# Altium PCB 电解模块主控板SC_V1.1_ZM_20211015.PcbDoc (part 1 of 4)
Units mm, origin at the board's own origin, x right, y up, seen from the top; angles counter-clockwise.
Board outline 150.25 x 100.26 mm, 2 copper layers (Top Layer, Bottom Layer); 222 components, 167 nets, 677 pads, 2045 vias.
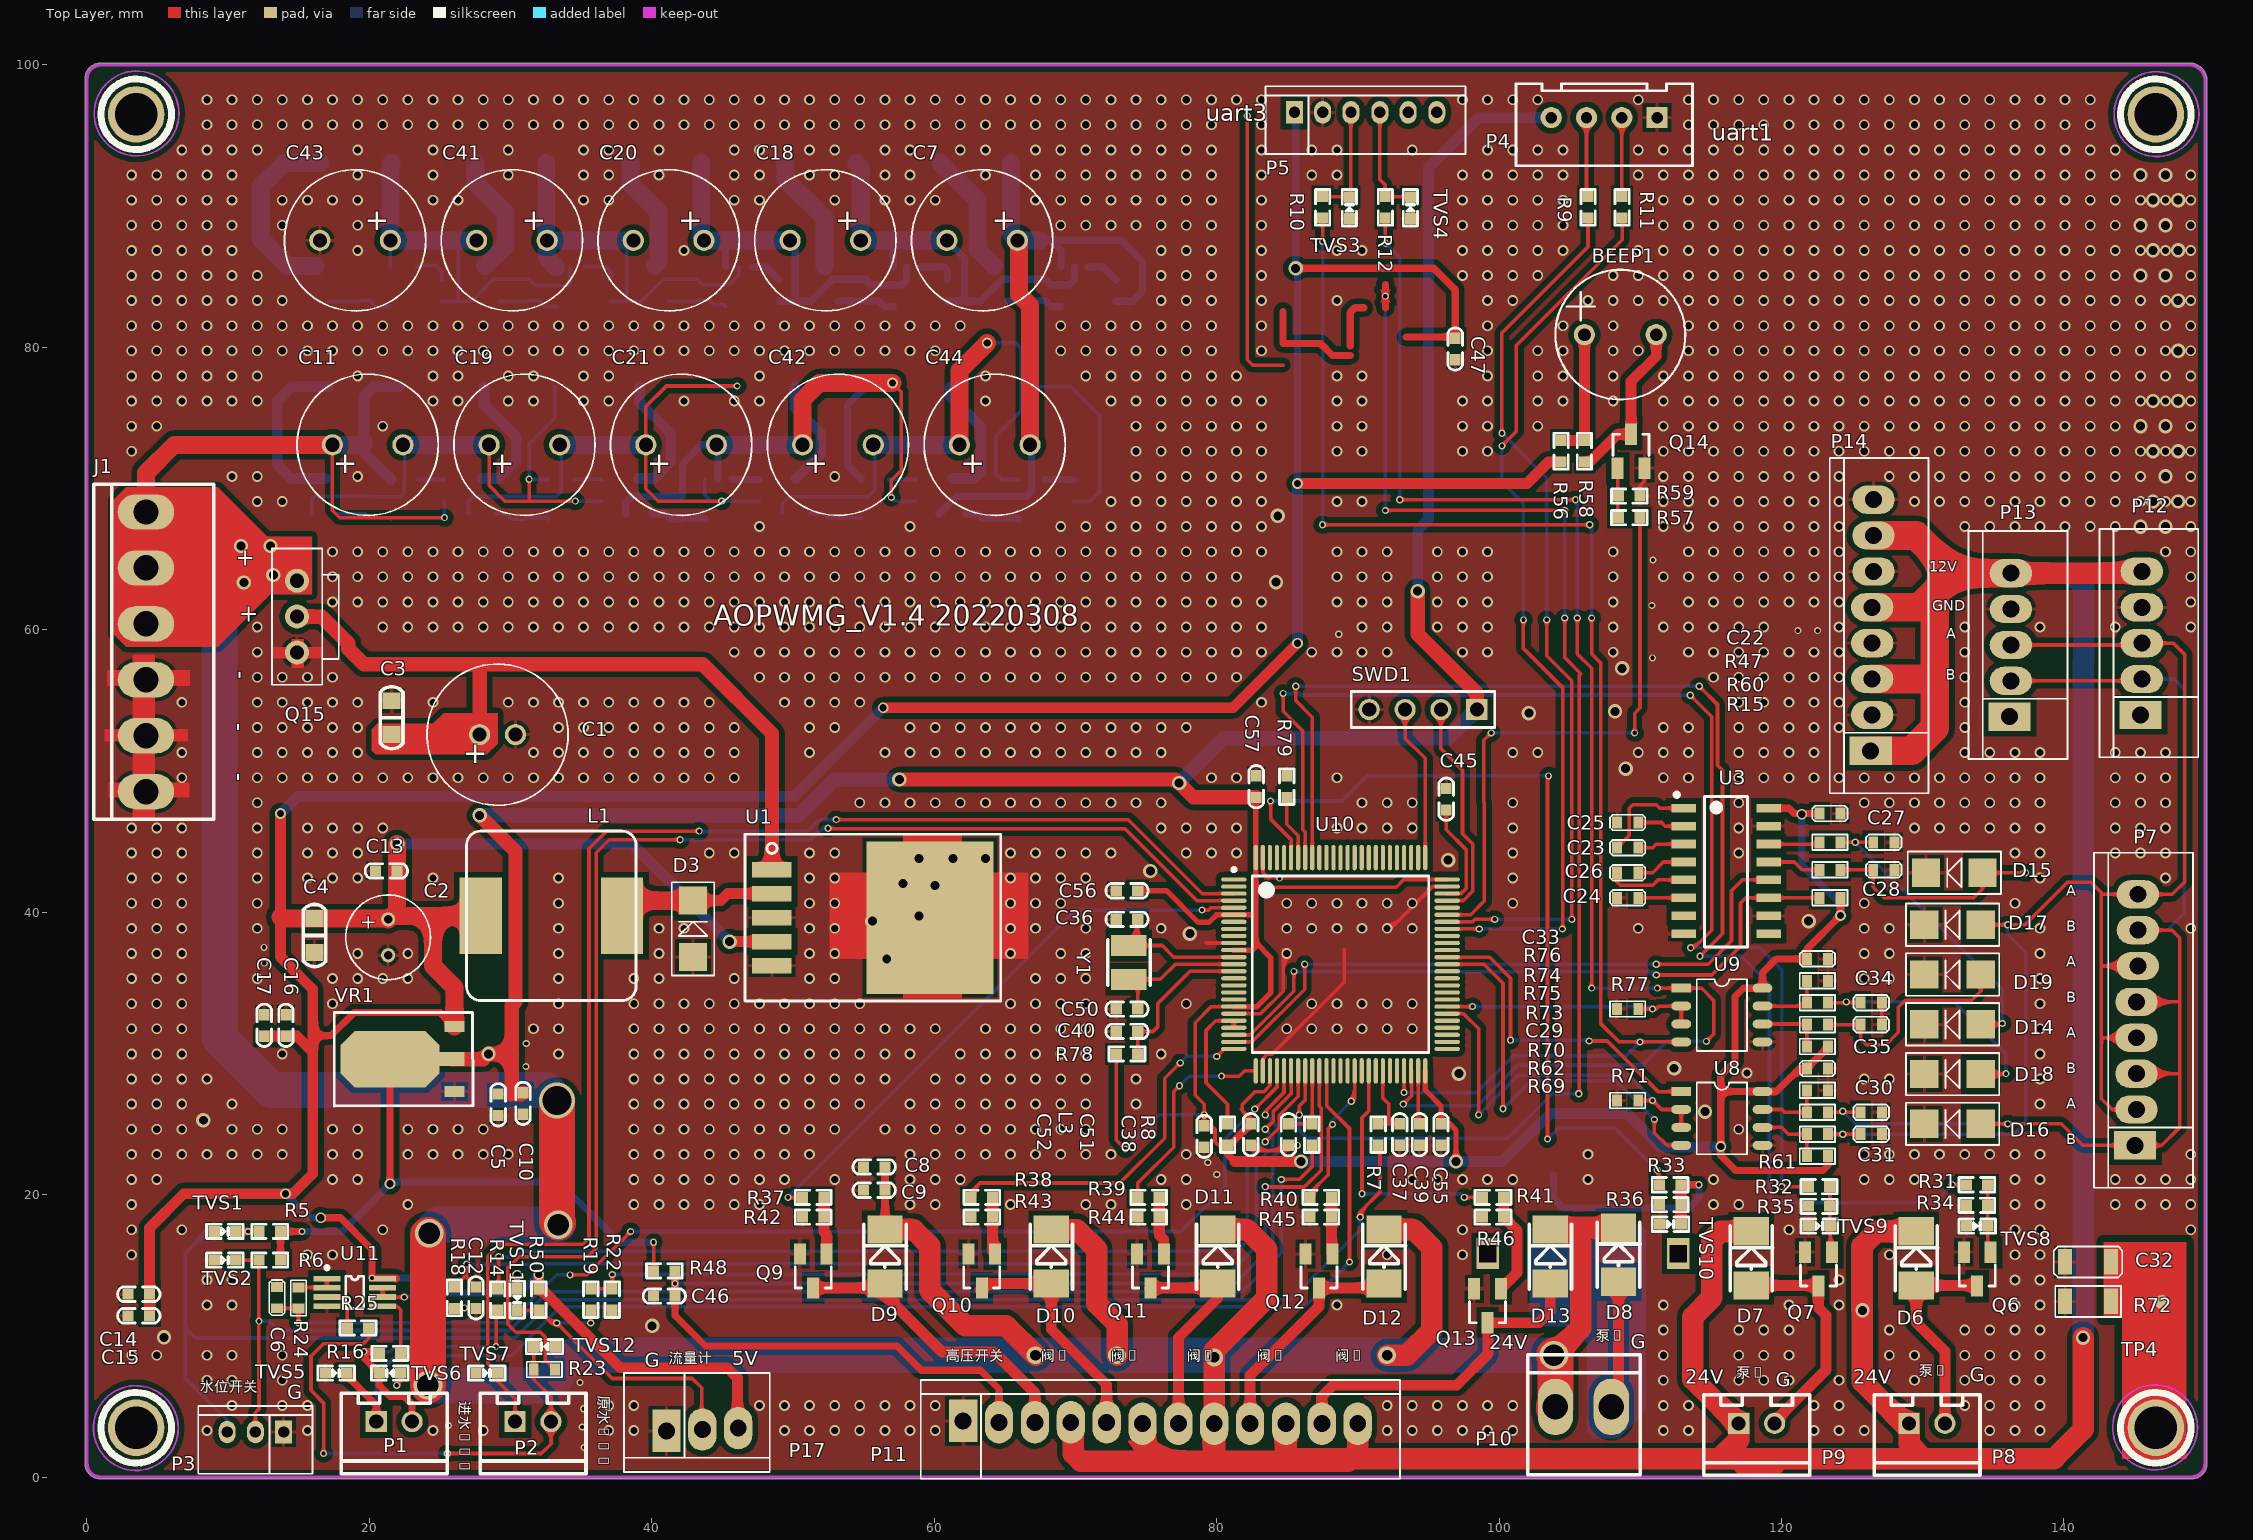
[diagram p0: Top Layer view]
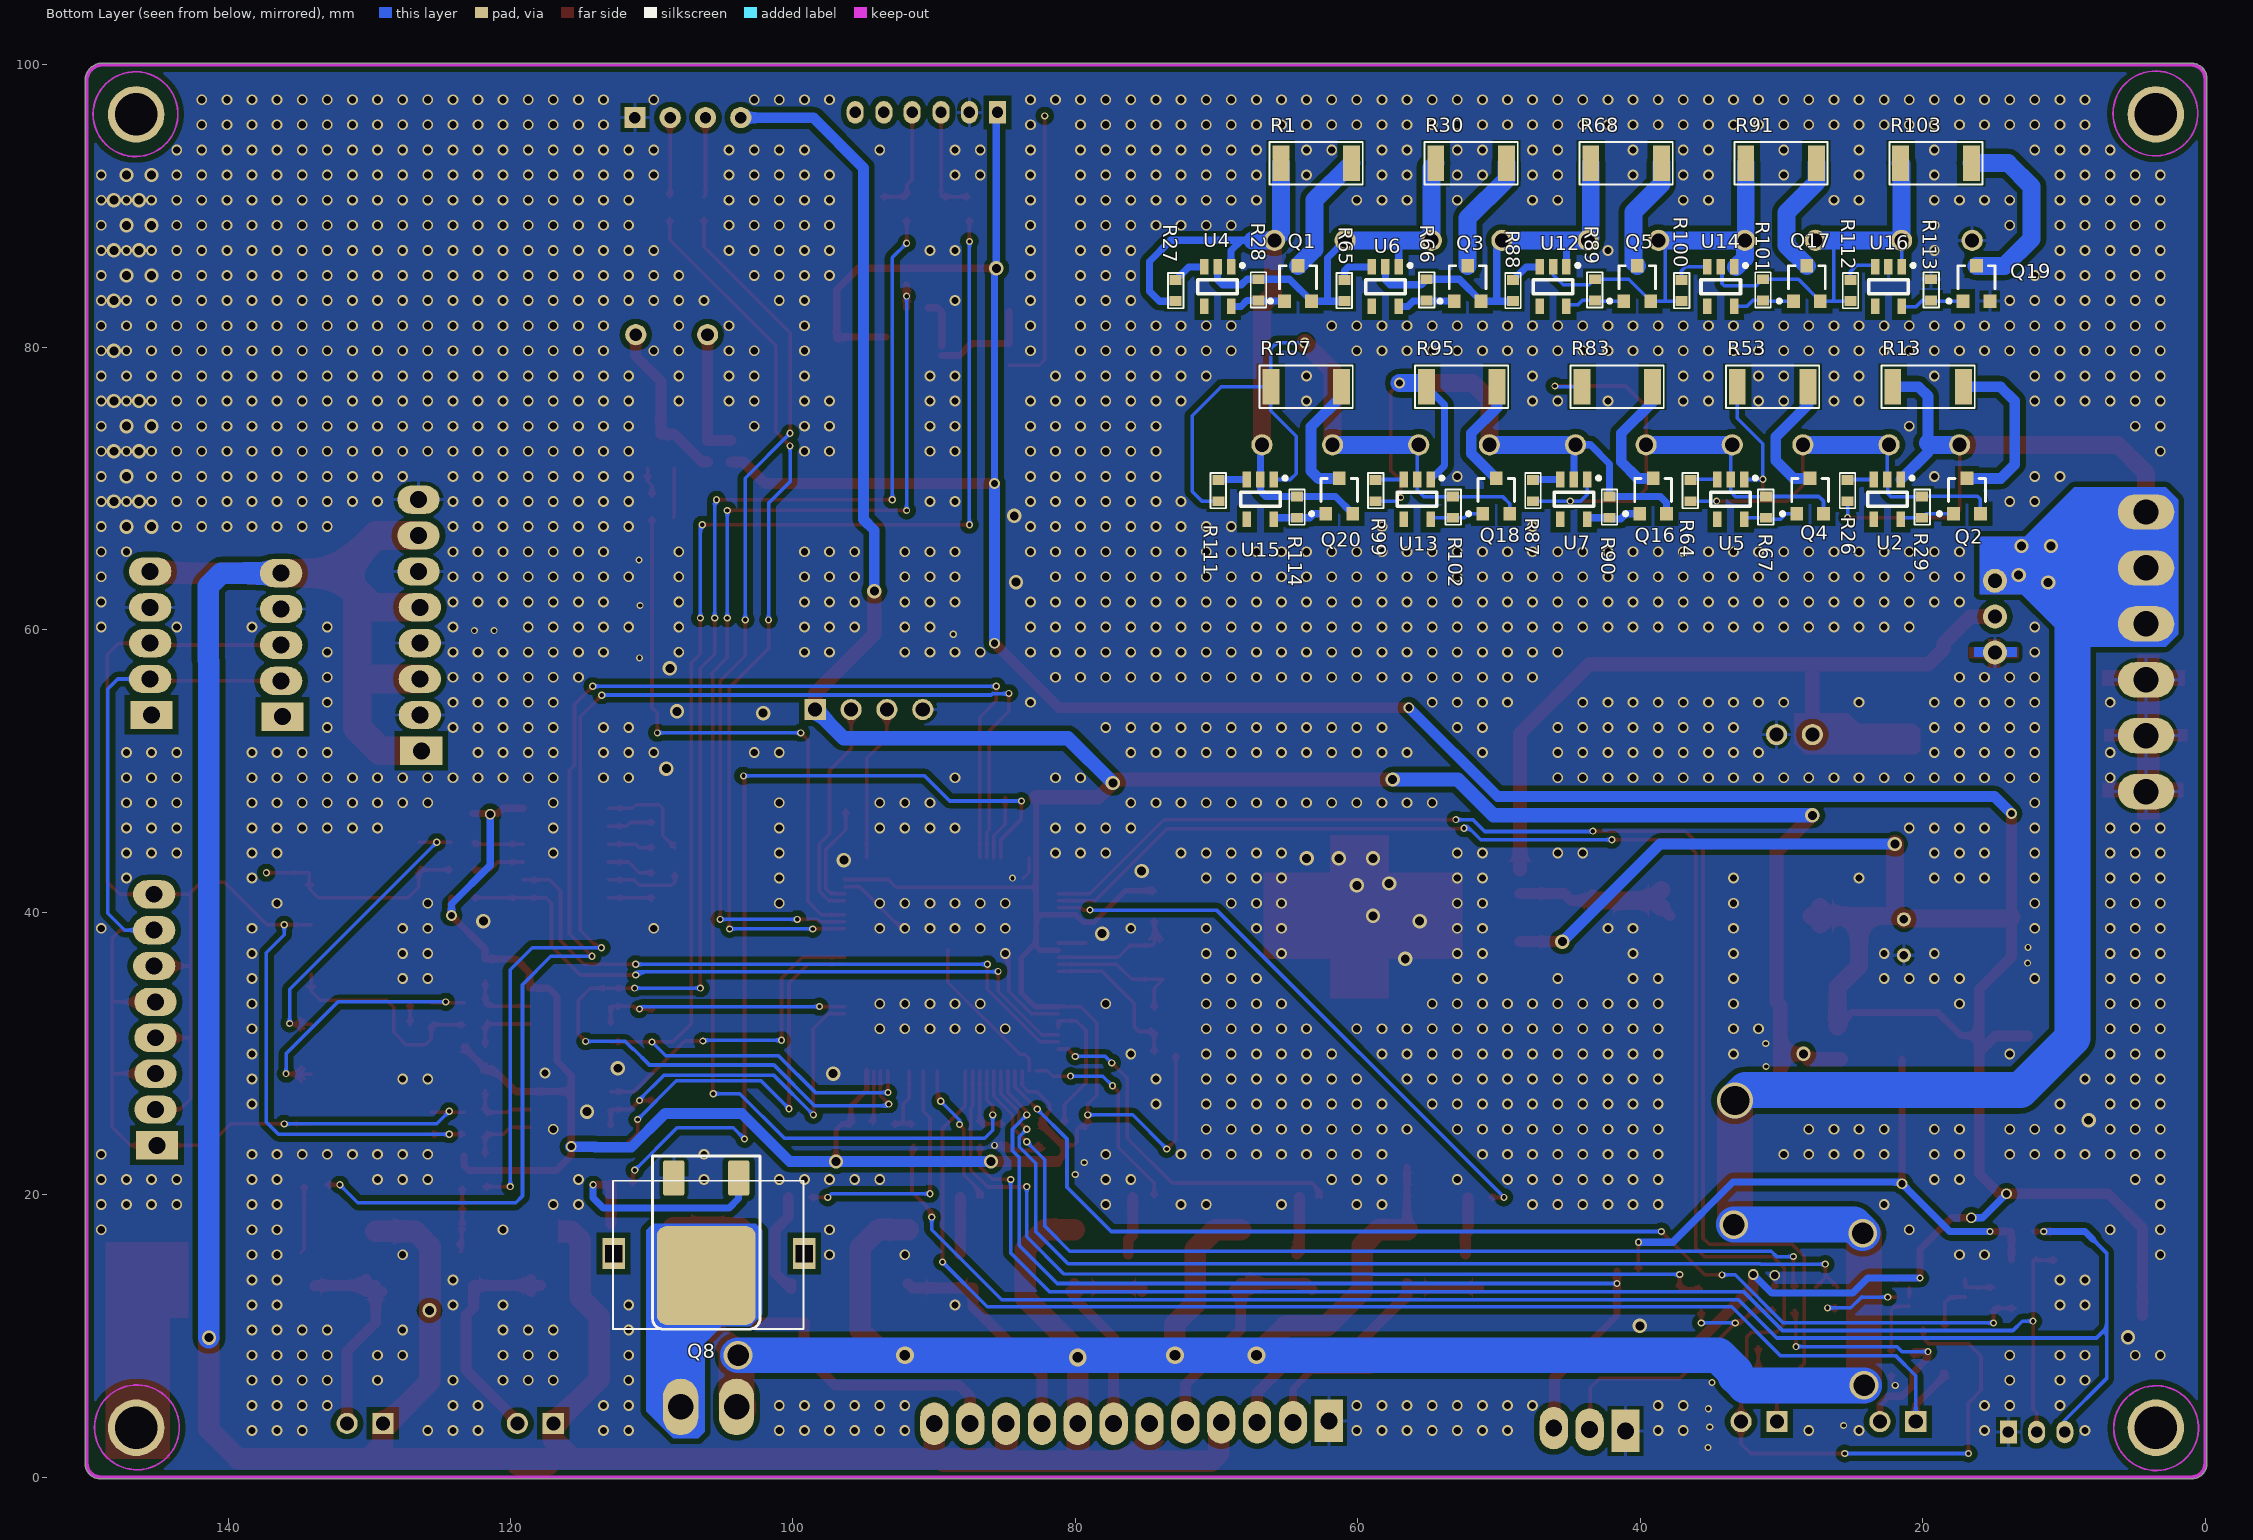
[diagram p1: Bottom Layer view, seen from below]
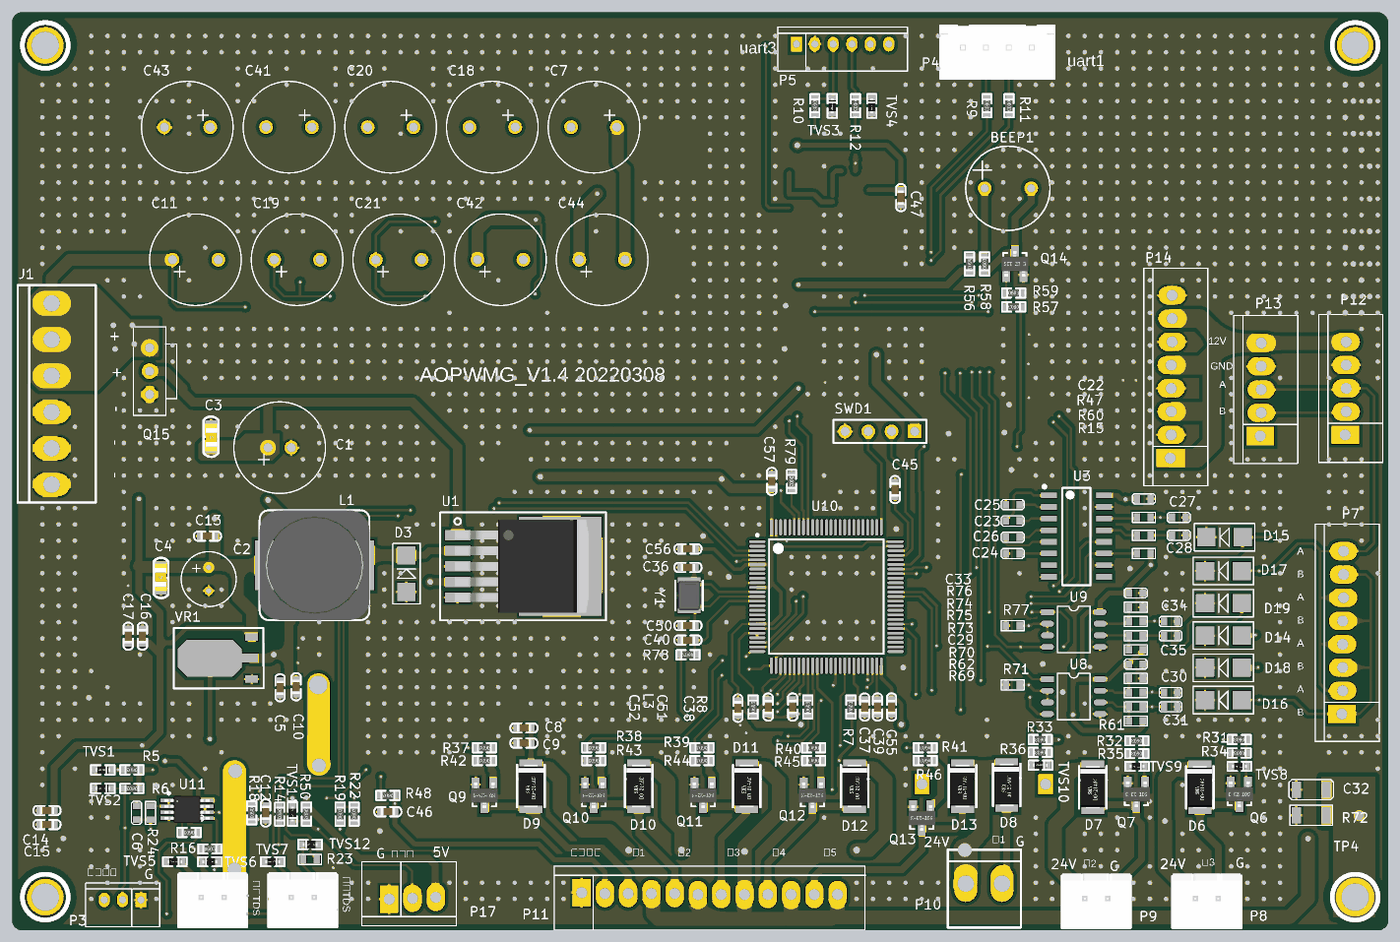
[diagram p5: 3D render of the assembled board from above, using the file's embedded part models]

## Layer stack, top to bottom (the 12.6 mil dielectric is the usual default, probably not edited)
Top Solder: solder mask 0.0102, Solder Resist, Dk 3.5
Top Layer: signal copper 0.0356
Dielectric1: dielectric 0.32, FR-4, Dk 4.8
Bottom Layer: signal copper 0.0356
Bottom Solder: solder mask 0.0102, Solder Resist, Dk 3.5

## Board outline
-0.127,1 ccw(c1,1) 1,-0.127 149,-0.127 ccw(c149,1) 150.127,1 150.127,99 ccw(c150,99) 150.126,99.016 ccw(c148.859,98.859) 148.709,100.127 1,100.127 ccw(c1,99) -0.127,99

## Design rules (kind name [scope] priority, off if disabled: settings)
Clearance Clearance_2 [InNet('NetC32_2')] p1: gap=0.508
Clearance Clearance_1 [InPolygon] p2: gap=0.381
Clearance [All] p3: gap=0.152
NetAntennae [All] p1: netantennaetolerance=5.08
PolygonConnect PolygonConnect_2 [InNet('NetC32_2')] p1: connectstyle=Direct reliefconductorwidth=0.254 reliefentries=4 polygonreliefangle="90 Angle" airgapwidth=0.254
PolygonConnect PolygonConnect_1 [isvia] p2: connectstyle=Direct reliefconductorwidth=0.254 reliefentries=4 polygonreliefangle="90 Angle" airgapwidth=0.254
PolygonConnect [All] p3: connectstyle=Relief reliefconductorwidth=0.254 reliefentries=4 polygonreliefangle="90 Angle" airgapwidth=0.254
RoutingVias [All] p1: holewidth=0.305 width=0.61 viastyle="Through Hole" minholewidth=0.203 minwidth=0.203 maxholewidth=5.08 maxwidth=5.08
SilkToSolderMaskClearance [IsPad] p1: minsilkscreentomaskgap=0.051 clearancetoexposedcopper=TRUE
SolderMaskExpansion [All] p1: expansion=0.102
Width [All] p1: maxlimit=9.144 minlimit=0.254 preferedwidth=0.254
28 further rules are at their usual default settings.

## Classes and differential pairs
component class 02_Power: C1 C2 C3 C4 C5 C8 C9 C10 C13 C14 C15 C16 C17 D3 J1 L1 Q15 U1 VR1
component class 04_Sensor: C6 C12 C37 C38 C47 P1 P2 P3 P17 R5 R6 R7 R8 R14 R16 R18 R19 R22 R23 R24 R25 R50 TVS1 TVS2 TVS5 TVS6 TVS7 TVS11 TVS12 U11
component class com: C22 C23 C24 C25 C26 C27 C28 C29 C30 C31 C32 C33 C34 C35 D14 D15 D16 D17 D18 D19 P7 P12 P13 P14 R15 R47 R60 R61 R62 R69 R70 R71 R72 R73 R74 R75 R76 R77 TP4 U3 U8 U9
component class 05_USART: P4 P5 R9 R10 R11 R12 TVS3 TVS4
component class cpu: C36 C39 C40 C45 C50 C51 C52 C55 C56 C57 L3 R78 R79 SWD1 U10 Y1
component class 08_Peripherals: C46 D6 D7 D8 D9 D10 D11 D12 D13 P8 P9 P10 P11 Q6 Q7 Q8 Q9 Q10 Q11 Q12 Q13 R31 R32 R33 R34 R35 R36 R37 R38 R39 R40 R41 R42 R43 R44 R45 R46 R48 TVS8 TVS9 TVS10
component class 11_Speak: BEEP1 BP1 Q14 R56 R57 R58 R59
component class 07_EL_CON: C7 C11 C18 C19 C20 C21 C41 C42 C43 C44 Q1 Q2 Q3 Q4 Q5 Q16 Q17 Q18 Q19 Q20 R1 R13 R26 R27 R28 R29 R30 R53 R64 R65 R66 R67 R68 R83 R87 R88 R89 R90 R91 R95 R99 R100 R101 R102 R103 R107 R111 R112 R113 R114 U2 U4 U5 U6 U7 U12 U13 U14 U15 U16

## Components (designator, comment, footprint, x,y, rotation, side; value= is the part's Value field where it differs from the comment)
BEEP1 "BEEP-9.5X5.5" BEEP-9.5X5.5 108.585,80.899 r0 top
C1 "1000uF/35V" 10*16 29.083,52.578 r180 top
C2 "100uF/35V" 6*8 21.336,38.227 r90 top
C3 "104 50V" SMD-0805C 21.59,53.778 r270 top
C4 "104 50V" SMD-0805C 16.129,38.354 r90 top
C5 "10uF 25V" SMD-0603C 29.134,26.365 r90 top
C6 "NC" 0603C 13.462,13.462 r270 top
C7 "1000uF/35V" "10*16 -5" 63.398,87.579 r0 top
C8 "10uF25V" SMD-0603C 55.753,21.971 r0 top
C9 "104 50V" SMD-0603C 55.753,20.32 r0 top
C10 "104 50V" SMD-0603C 30.886,26.467 r90 top
C11 "1000uF/35V" "10*16 -5" 19.888,73.101 r180 top
C12 "NC" SMD-0603C 27.559,12.7 r90 top
C13 "104 50V" SMD-0603C 21.209,42.926 r0 top
C14 "10uF25V" SMD-0603C 3.683,12.954 r0 top
C15 "104 50V" SMD-0603C 3.683,11.43 r0 top
C16 "10uF25V" SMD-0603C 14.097,31.991 r270 top
C17 "104 50V" SMD-0603C 12.56,31.991 r270 top
C18 "1000uF/35V" "10*16 -5" 52.299,87.579 r0 top
C19 "1000uF/35V" "10*16 -5" 30.988,73.101 r180 top
C20 "1000uF/35V" "10*16 -5" 41.199,87.579 r0 top
C21 "1000uF/35V" "10*16 -5" 42.088,73.101 r180 top
C22 "104 50V" 0603C 122.682,46.99 r0 top
C23 "104 50V" 0603C 108.355,44.577 r0 top
C24 "104 50V" 0603C 109.855,41.021 r180 top
C25 "104 50V" 0603C 109.855,46.355 r180 top
C26 "104 50V" 0603C 108.355,42.799 r0 top
C27 "220PF/16V" 0603C 126.492,44.958 r0 top
C28 "220PF/16V" 0603C 126.492,43.011 r0 top
C29 "104 50V" 0603C 121.793,28.942 r0 top
C30 "220PF/16V" 0603C 125.603,25.837 r0 top
C31 "220PF/16V" 0603C 125.603,24.285 r0 top
C32 "1NF/2KV" 1206C 140.081,15.24 r0 top
C33 "104 50V" 0603C 121.793,36.703 r0 top
C34 "220PF/16V" 0603C 125.603,33.599 r0 top
C35 "220PF/16V" 0603C 125.603,32.046 r0 top
C36 "12P/50V" SMD-0603C 73.66,39.497 r180 top
C37 "104 50V" SMD-0603C 92.964,24.257 r90 top
C38 "104 50V" SMD-0603C 85.09,24.257 r90 top
C39 "4.7uF/10V/NC" SMD-0603C 94.361,24.257 r90 top
C40 "1uF/10V" SMD-0603C 73.66,31.559 r0 top
C41 "1000uF/35V" "10*16 -5" 30.099,87.579 r0 top
C42 "1000uF/35V" "10*16 -5" 53.188,73.101 r180 top
C43 "1000uF/35V" "10*16 -5" 18.999,87.579 r0 top
C44 "1000uF/35V" "10*16 -5" 64.287,73.101 r180 top
C45 "4.7uF/10V/NC" SMD-0603C 96.266,48.006 r270 top
C46 "104 50V" SMD-0603C 40.894,12.827 r0 top
C47 "10uF 10V" SMD-0603C 96.901,79.883 r90 top
C50 "12P/50V" SMD-0603C 73.66,33.147 r180 top
C51 "104 50V" SMD-0603C 82.423,24.257 r90 top
C52 "104 50V" SMD-0603C 79.121,24.13 r90 top
C55 "104 50V" SMD-0603C 95.885,24.257 r90 top
C56 "104 50V" SMD-0603C 73.66,41.529 r0 top
C57 "104 50V" SMD-0603C 82.804,48.895 r270 top
D3 "SS34" SMA 42.926,36.83 r90 top
D6 "1N4007" DO-214-AC 129.54,15.494 r90 top
D7 "1N4007" DO-214-AC 117.856,15.494 r90 top
D8 "1N4007" DO-214-AC 108.458,15.748 r90 top
D9 "1N4007" DO-214-AC 56.515,15.621 r90 top
D10 "1N4007" DO-214-AC 68.294,15.621 r90 top
D11 "1N4007" DO-214-AC 80.073,15.621 r90 top
D12 "1N4007" DO-214-AC 91.853,15.621 r90 top
D13 "1N4007" DO-214-AC 103.632,15.621 r90 top
D14 "SMAJ18CA" SMA 134.112,32.067 r180 top
D15 "SMAJ18CA" SMA 134.239,42.799 r180 top
D16 "SMAJ6.5CA" SMA 134.112,25.019 r180 top
D17 "SMAJ6.5CA" SMA 134.112,39.116 r180 top
D18 "SMAJ6.5CA" SMA 134.112,28.543 r180 top
D19 "SMAJ6.5CA" SMA 134.112,35.592 r180 top
J1 "HEADER_6" VH-AW-3.96*6P 4.191,54.483 r90 top
L1 "CDRH127-33uH" CDRH-127 32.893,39.751 r180 top
L3 "MPZ1608D101BTA00" SMD-0603 80.772,24.257 r90 top
P1 "XH2.54 2P" SIP-2A 21.768,3.937 r0 top
P2 "XH2.54 2P" SIP-2A 31.598,3.937 r0 top
P3 "1*3P" 3X2MMZ 13.938,3.2 r180 top
P4 "1*4P" XH2.54-4A 107.442,96.266 r180 top
P5 "Header 6" 6X2MMZ 85.511,96.641 r0 top
P7 "Header 8" 8X2.54MMZ 145.034,23.495 r90 top
P8 "SIP-2" SIP-2A 130.302,3.81 r0 top
P9 "SIP-2" SIP-2A 118.237,3.81 r0 top
P10 "SIP-2" VH-AW-3.96*2P 109.93,4.978 r0 top
P11 "Header 12" 12X2.54MMZ 62.052,3.988 r0 top
P12 "Header 5" 5X2.54MMZ 145.415,53.975 r90 top
P13 "Header 5" 5X2.54MMZ 136.144,53.848 r90 top
P14 "Header 8" 8X2.54MMZ 126.316,51.435 r90 top
P17 "1*3P" 3X2.54MMZ2 41.046,3.277 r0 top
Q1 "AO3400" SOT-23#1 64.237,84.525 r180 bottom
Q2 "AO3400" SOT-23#1 16.866,69.469 r180 bottom
Q3 "AO3400" SOT-23#1 52.226,84.525 r180 bottom
Q4 "AO3400" SOT-23#1 27.978,69.469 r180 bottom
Q5 "AO3400" SOT-23#1 40.216,84.525 r180 bottom
Q6 "AO3400" SOT-23#2 133.858,14.732 r180 top
Q7 "AO3400" SOT-23#2 122.618,14.732 r180 top
Q8 "AOD538" TO252 106.135,14.284 r0 bottom
Q9 "AO3400" SOT-23#2 51.435,14.605 r180 top
Q10 "AO3400" SOT-23#2 63.373,14.605 r180 top
Q11 "AO3400" SOT-23#2 75.311,14.605 r180 top
Q12 "AO3400" SOT-23#2 87.249,14.605 r180 top
Q13 "AO3400" SOT-23#2 99.187,12.141 r180 top
Q14 "LH8050QLT1G" SOT-23#2 109.347,72.644 r0 top
Q15 "AOTF4185" TO220 14.884,58.395 r90 top
Q16 "AO3400" SOT-23#1 39.091,69.469 r180 bottom
Q17 "AO3400" SOT-23#1 28.205,84.525 r180 bottom
Q18 "AO3400" SOT-23#1 50.203,69.469 r180 bottom
Q19 "AO3400" SOT-23#1 16.195,84.525 r180 bottom
Q20 "AO3400" SOT-23#1 61.316,69.469 r180 bottom
R1 "4.7" 2010R 65.456,93.04 r180 bottom
R5 "10K" SMD-0603 12.954,17.399 r180 top
R6 "10K" SMD-0603 12.954,15.367 r180 top
R7 "10K" SMD-0603 91.44,24.257 r90 top
R8 "10K" SMD-0603 86.741,24.257 r90 top
R9 "10R" SMD-0603 106.299,89.916 r270 top
R10 "100R" SMD-0603 87.503,89.916 r270 top
R11 "10R" SMD-0603 108.712,89.916 r270 top
R12 "100R" SMD-0603 91.948,89.916 r270 top
R13 "4.7" 2010R 22.123,77.216 r180 bottom
R14 "2K" SMD-0603 29.083,12.573 r270 top
R15 "4.75K 1%" 0603R 124.182,41.021 r180 top
R16 "10K" SMD-0603 21.463,8.763 r0 top
R18 "4.7K" SMD-0603 26.035,12.7 r270 top
R19 "10K" SMD-0603 35.687,12.573 r90 top
R22 "20K" SMD-0603 37.211,12.573 r90 top
R23 "2K" 0603R 33.147,7.62 r180 top
R24 "4.7K" 0603R 14.986,11.938 r90 top
R25 "10K" SMD-0603 19.202,10.566 r180 top
R26 "1K" 0603R 25.324,69.105 r90 bottom
R27 "1K" 0603R 72.898,83.272 r90 bottom
R28 "1K" 0603R 67.031,83.322 r90 bottom
R29 "1K" 0603R 20.041,67.937 r90 bottom
R30 "4.7" 2010R 54.482,93.04 r180 bottom
R31 "100R" SMD-0603 133.833,20.701 r180 top
R32 "100R" SMD-0603 122.657,20.574 r180 top
R33 "100R" SMD-0603 112.116,20.701 r180 top
R34 "10K" SMD-0603 133.833,19.241 r180 top
R35 "10K" SMD-0603 122.657,19.177 r180 top
R36 "10K" SMD-0603 112.116,19.304 r180 top
R37 "1K" SMD-0603 51.435,19.812 r180 top
R38 "1K" SMD-0603 63.373,19.812 r180 top
R39 "1K" SMD-0603 75.184,19.812 r180 top
R40 "1K" SMD-0603 87.376,19.812 r180 top
R41 "1K" SMD-0603 99.568,19.812 r180 top
R42 "10K" SMD-0603 51.435,18.415 r180 top
R43 "10K" SMD-0603 63.373,18.415 r180 top
R44 "10K" SMD-0603 75.184,18.415 r180 top
R45 "10K" SMD-0603 87.376,18.415 r180 top
R46 "10K" SMD-0603 99.568,18.415 r180 top
R47 "22R 5%" 0603R 122.682,44.958 r0 top
R48 "10K" SMD-0603 40.894,14.605 r180 top
R50 "10K" SMD-0603 32.004,12.573 r270 top
R53 "4.7" 2010R 33.133,77.216 r180 bottom
R56 "51R" SMD-0603 104.394,72.644 r270 top
R57 "4.7K" SMD-0603 109.22,67.945 r180 top
R58 "1K" SMD-0603 106.045,72.644 r90 top
R59 "47K" SMD-0603 109.22,69.469 r0 top
R60 "22R 5%" 0603R 122.682,43.011 r0 top
R61 "750R 5%" 0603R 121.793,22.733 r0 top
R62 "FSMD010-0603" 0603R 121.793,25.837 r0 top
R64 "1K" 0603R 36.462,69.105 r90 bottom
R65 "1K" 0603R 60.954,83.272 r90 bottom
R66 "1K" 0603R 55.124,83.322 r90 bottom
R67 "1K" 0603R 31.109,67.937 r90 bottom
R68 "4.7" 2010R 43.508,93.04 r180 bottom
R69 "FSMD010-0603" 0603R 121.793,24.285 r0 top
R70 "750R 5%" 0603R 121.793,27.39 r0 top
R71 "10K 1%" 0603R 109.855,26.67 r180 top
R72 "10M 5%" 1206r 140.081,12.446 r0 top
R73 "750R 5%" 0603R 121.793,30.494 r0 top
R74 "FSMD010-0603" 0603R 121.793,33.599 r0 top
R75 "FSMD010-0603" 0603R 121.793,32.046 r0 top
R76 "750R 5%" 0603R 121.793,35.151 r0 top
R77 "10K 1%" 0603R 109.855,33.147 r180 top
R78 "10K" SMD-0603 73.66,29.972 r180 top
R79 "100K" SMD-0603 84.963,48.895 r270 top
R83 "4.7" 2010R 44.143,77.216 r180 bottom
R87 "1K" 0603R 47.6,69.105 r90 bottom
R88 "1K" 0603R 49.009,83.272 r90 bottom
R89 "1K" 0603R 43.218,83.322 r90 bottom
R90 "1K" 0603R 42.177,67.937 r90 bottom
R91 "4.7" 2010R 32.535,93.04 r180 bottom
R95 "4.7" 2010R 55.153,77.216 r180 bottom
R99 "1K" 0603R 58.737,69.105 r90 bottom
R100 "1K" 0603R 37.065,83.272 r90 bottom
R101 "1K" 0603R 31.312,83.322 r90 bottom
R102 "1K" 0603R 53.245,67.937 r90 bottom
R103 "4.7" 2010R 21.561,93.04 r180 bottom
R107 "4.7" 2010R 66.163,77.216 r180 bottom
R111 "1K" 0603R 69.875,69.105 r90 bottom
R112 "1K" 0603R 25.121,83.272 r90 bottom
R113 "1K" 0603R 19.406,83.322 r90 bottom
R114 "1K" 0603R 64.313,67.937 r90 bottom
SWD1 "SIP-4 (NC)" SIP-4 94.615,54.356 r180 top
TP4 "TPS" tpd 146.939,12.395 r90 top
TVS1 "ESD5Z5.0CT1G" SOD-523 9.779,17.399 r0 top
TVS2 "ESD5Z5.0CT1G" SOD-523 9.779,15.367 r0 top
TVS3 "ESD5Z5.0CT1G" SOD-523 89.408,89.891 r90 top
TVS4 "ESD5Z5.0CT1G" SOD-523 93.726,89.891 r90 top
TVS5 "ESD5Z5.0CT1G" SOD-523 17.653,7.366 r0 top
TVS6 "ESD5Z5.0CT1G" SOD-523 21.463,7.366 r180 top
TVS7 "ESD5Z5.0CT1G" SOD-523 28.321,7.366 r0 top
TVS8 "ESD5Z5.0CT1G" SOD-523 133.858,17.78 r0 top
TVS9 "ESD5Z5.0CT1G" SOD-523 122.682,17.78 r0 top
TVS10 "ESD5Z5.0CT1G" SOD-523 112.141,17.907 r0 top
TVS11 "ESD5Z5.0CT1G" SOD-523 30.48,12.573 r270 top
TVS12 "ESD5Z5.0CT1G" SOD-523 32.41,9.246 r180 top
U1 "LM2596S 5.0V" TO-263-5 48.514,39.624 r270 top
U2 "B W 6101" SOT23-5 22.504,69.244 r270 bottom
U3 "TPT3232E-SO3R" SO-16Z 113.068,47.371 r0 top
U4 "B W 6101" SOT23-5 69.926,84.3 r270 bottom
U5 "B W 6101" SOT23-5 33.604,69.244 r270 bottom
U6 "B W 6101" SOT23-5 58.052,84.3 r270 bottom
U7 "B W 6101" SOT23-5 44.704,69.244 r270 bottom
U8 "TP8485E-SR/NC" SO-8 112.903,27.305 r0 top
U9 "TP8485E-SR" SO-8 112.903,34.629 r0 top
U10 "GD32F405VGTx" STM-LQFP100_N 88.773,36.322 r0 top
U11 "SGM358YMS/TR" MSOP-8 18.974,13.081 r0 top
U12 "B W 6101" SOT23-5 46.177,84.3 r270 bottom
U13 "B W 6101" SOT23-5 55.804,69.244 r270 bottom
U14 "B W 6101" SOT23-5 34.303,84.3 r270 bottom
U15 "B W 6101" SOT23-5 66.904,69.244 r270 bottom
U16 "B W 6101" SOT23-5 22.428,84.3 r270 bottom
VR1 "LM1117 3.3V" SOT223 26.035,27.305 r90 top
Y1 "8MHz" XTAL-3225-2 73.787,36.449 r90 top

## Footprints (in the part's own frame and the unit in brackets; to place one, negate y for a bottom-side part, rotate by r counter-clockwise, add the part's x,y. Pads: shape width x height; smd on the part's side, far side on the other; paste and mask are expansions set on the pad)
3X2.54MMZ2 [mm]
  rect 2x3 hole 1.2: 1(0,0)
  oval 2x3 hole 1.2: 2(2.54,0.1) 3(5.08,0.2)
  silkscreen extent -3,-2.9 7.31,4.1
3X2MMZ [mm]
  rect 1.2x1.6 hole 0.8: 1(0,0)
  oval 1.2x1.6 hole 0.8: 2(2,0) 3(4,0)
  silkscreen extent -2.05,-1.85 6.05,2.95
5X2.54MMZ [mm]
  rect 2x3 hole 1.2: 1(0,0)
  oval 2x3 hole 1.2: 2(2.54,-0.1) 3(5.08,-0.1) 4(7.62,-0.1) 5(10.16,-0.1)
  silkscreen extent -3,-4.1 13.16,2.9
6*8 [mm]
  round 1 hole 0.6: 1(1.27,0) 2(-1.27,0)
  silkscreen extent -3,-3 3,3
6X2MMZ [mm]
  rect 1.2x1.6 hole 0.8: 1(0,0)
  oval 1.2x1.6 hole 0.8: 2(2,0) 3(4,0) 4(6.05,0) 5(8.05,0) 6(10.08,0)
  silkscreen extent -2.05,-2.95 12.12,1.85
8X2.54MMZ [mm]
  rect 2x3 hole 1.2: 1(0,0)
  oval 2x3 hole 1.2: 2(2.54,-0.1) 3(5.08,-0.1) 4(7.62,-0.1) 5(10.16,-0.1) 6(12.7,-0.2) 7(15.24,-0.2) 8(17.78,-0.2)
  silkscreen extent -3,-4.1 20.73,2.9
10*16 [mm]
  round 1.5 hole 1: 1(1.27,0) 2(-1.27,0)
  silkscreen extent -5,-5 5,5
"10*16 -5" [mm]
  round 1.5 hole 1: 1(2.5,0) 2(-2.5,0)
  silkscreen extent -5,-5 5,5
12X2.54MMZ [mm]
  rect 2x3 hole 1.2: 1(0,0)
  oval 2x3 hole 1.2: 2(2.54,-0.1) 3(5.08,-0.1) 4(7.62,-0.1) 5(10.16,-0.1) 6(12.7,-0.2) 7(15.24,-0.2) 8(17.78,-0.2) 9(20.32,-0.2) 10(22.86,-0.2) 11(25.4,-0.2) 12(27.94,-0.2)
  silkscreen extent -3,-4.1 30.99,2.9
0603C [mm]
  rect 0.7x0.85 smd: 1(0,0) 2(1.5,0)
  silkscreen extent -0.5,-0.55 2,0.55
0603R [mm]
  rect 0.7x0.85 smd: 1(0,0) 2(1.5,0)
  silkscreen extent -0.5,-0.55 2,0.55
1206C [mm]
  rect 1x1.8 smd: 1(0,0) 2(3.25,0)
  silkscreen extent -0.8,-1.1 4.05,1.1
1206r [mm]
  rect 1x1.8 smd: 1(0,0) 2(3.25,0)
  silkscreen extent -0.7,-1.1 3.95,1.1
2010R [mm]
  rect 1.2x2.5 smd: 1(0,0) 2(5,0)
  silkscreen extent -0.8,-1.5 5.8,1.5
BEEP-9.5X5.5 [mm]
  round 1.5 hole 0.9: 1(-2.54,0) 2(2.54,0)
  silkscreen extent -4.6,-4.6 4.6,4.6
CDRH-127 [mm]
  rect 3x5.4 smd: 1(-5,0) 2(5,0)
  silkscreen extent -6,-6 6,6, body extent -6,-6 6,6, height 8.2
DO-214-AC [mm]
  rect 2x2.5 smd: 1(-1.915,0) 2(1.915,0)
  silkscreen extent -2.3,-1.52 2.3,1.5, body extent -2.3,-1.35 2.3,1.35, height 2.4
MSOP-8 [mm]
  rect 1.9x0.4 smd: 1(-1.975,0.975) 2(-1.975,0.325) 3(-1.975,-0.325) 4(-1.975,-0.975) 5(1.975,-0.975) 6(1.975,-0.325) 7(1.975,0.325) 8(1.975,0.975)
  silkscreen extent -2.1,-1.14 0.64,1.87, body extent -2.45,-1.5 2.45,1.5, height 1.15
SIP-2A [mm]
  rect 1.5x1.5 hole 1: 1(-1.27,0)
  round 1.5 hole 1: 2(1.27,0)
  silkscreen extent -3.75,-3.68 3.75,2.02, body extent -3.7,-3.81 3.7,2.29, height 7.5
SIP-4 [mm]
  rect 1.5x1.5 hole 1: 1(-3.81,0)
  round 1.5 hole 1: 2(-1.27,0) 3(1.27,0) 4(3.81,0)
  silkscreen extent -5.08,-1.27 5.08,1.27
SMA [mm]
  rect 2x2 smd: 1(0,0) 2(4,0)
  silkscreen extent -1.3,-1.5 5.3,1.5
SMD-0603 [mil]
  rect 31.5x30 smd: 1(-30,0) 2(30,0)
  silkscreen extent -50,-20 50,20, body extent -31,-16 31,16, height 18
SMD-0603C [mil] "贴片电容"
  rect 31.5x30 smd: 1(-30,0) 2(30,0)
  silkscreen extent -59,-20 59,20, body extent -31,-16 31,16
SMD-0805C [mm]
  rect 1.2x1.27 smd: 1(-1.2,0) 2(1.2,0)
  silkscreen extent -2.2,-0.8 2.2,0.8, body extent -1.42,-0.67 1.58,0.73, height 0.93
SO-8 [mil]
  rect 55x25 smd: 1(0,0)
  oval 55x25 smd: 2(0,-50) 3(0,-100) 4(0,-150) 5(226.38,-150) 6(226.38,-100) 7(226.38,-50) 8(226.38,0)
  silkscreen extent 43,-175 183,25
SO-16Z [mil]
  rect 68x24 smd: 1(0,0) 2(0,-50) 3(0,-100) 4(0,-150) 5(0,-200) 6(0,-250) 7(0,-300) 8(0,-350) 9(237.11,-350) 10(237.11,-300) 11(237.11,-250) 12(237.11,-200) 13(237.11,-150) 14(237.11,-100) 15(237.11,-50) 16(237.11,0)
  silkscreen extent -19,-387 178,38
SOD-523 [mil]
  rect 31.5x30 smd: 1(-30,0) 2(30,0)
  silkscreen extent -51,-20 51,20, body extent -31,-16 31,16, height 26
SOT23-5 [mm]
  rect 1.1x0.6 smd: 1(-1.4,0.95) 2(-1.4,0) 3(-1.4,-0.95) 4(1.4,-0.95) 5(1.4,0.95)
  silkscreen extent -1.62,-1.4 0.5,1.87, body extent -1.25,-1.5 1.25,1.5, height 1.1
SOT223 [mm]
  rect 0.8x1.4 smd: 1(0,0) 3(4.6,0)
  rect 1x1.854 smd: 2(2.3,0.227)
  oct 4x7 smd: 4(2.286,4.572)
  silkscreen extent -1.02,-1.3 5.59,8.51
SOT-23#1 [mm] "SOT-23; 3 Leads; Body 3.0 x 2.6 mm, inc. leads (LxW max)"
  rect 0.9x0.95 smd: 1(-0.95,-1.25) 2(0.95,-1.25) 3(0,1.25)
  silkscreen extent -2.08,-1.37 1.3,1.25
SOT-23#2 [mm]
  rect 0.85x1.5 smd: 1(-0.95,-1.2) 2(0.95,-1.2) 3(0,1.2)
  silkscreen extent -1.27,-0.3 1.28,1.2, body extent -1.45,-1.4 1.45,1.4, height 1.2
STM-LQFP100_N [mm] "Thin QFP, 100-Leads, Body 14x14mm, Pitch 0.5mm, IPC Medium Density"
  oval 1.8x0.3 smd: 1(-7.55,6) 2(-7.55,5.5) 3(-7.55,5) 4(-7.55,4.5) 5(-7.55,4) 6(-7.55,3.5) 7(-7.55,3) 8(-7.55,2.5) 9(-7.55,2) 10(-7.55,1.5) 11(-7.55,1) 12(-7.55,0.5) 13(-7.55,0) 14(-7.55,-0.5) 15(-7.55,-1) 16(-7.55,-1.5) 17(-7.55,-2) 18(-7.55,-2.5) 19(-7.55,-3) 20(-7.55,-3.5) 21(-7.55,-4) 22(-7.55,-4.5) 23(-7.55,-5) 24(-7.55,-5.5) 25(-7.55,-6) 51(7.55,-6) 52(7.55,-5.5) 53(7.55,-5) 54(7.55,-4.5) 55(7.55,-4) 56(7.55,-3.5) 57(7.55,-3) 58(7.55,-2.5) 59(7.55,-2) 60(7.55,-1.5) 61(7.55,-1) 62(7.55,-0.5) 63(7.55,0) 64(7.55,0.5) 65(7.55,1) 66(7.55,1.5) 67(7.55,2) 68(7.55,2.5) 69(7.55,3) 70(7.55,3.5) 71(7.55,4) 72(7.55,4.5) 73(7.55,5) 74(7.55,5.5) 75(7.55,6)
  oval 0.3x1.8 smd: 26(-6,-7.55) 27(-5.5,-7.55) 28(-5,-7.55) 29(-4.5,-7.55) 30(-4,-7.55) 31(-3.5,-7.55) 32(-3,-7.55) 33(-2.5,-7.55) 34(-2,-7.55) 35(-1.5,-7.55) 36(-1,-7.55) 37(-0.5,-7.55) 38(0,-7.55) 39(0.5,-7.55) 40(1,-7.55) 41(1.5,-7.55) 42(2,-7.55) 43(2.5,-7.55) 44(3,-7.55) 45(3.5,-7.55) 46(4,-7.55) 47(4.5,-7.55) 48(5,-7.55) 49(5.5,-7.55) 50(6,-7.55) 76(6,7.55) 77(5.5,7.55) 78(5,7.55) 79(4.5,7.55) 80(4,7.55) 81(3.5,7.55) 82(3,7.55) 83(2.5,7.55) 84(2,7.55) 85(1.5,7.55) 86(1,7.55) 87(0.5,7.55) 88(0,7.55) 89(-0.5,7.55) 90(-1,7.55) 91(-1.5,7.55) 92(-2,7.55) 93(-2.5,7.55) 94(-3,7.55) 95(-3.5,7.55) 96(-4,7.55) 97(-4.5,7.55) 98(-5,7.55) 99(-5.5,7.55) 100(-6,7.55)
  silkscreen extent -7.67,-6.25 6.25,6.82, body extent -7,-7 7,7, height 1.6
TO220 [mm]
  round 1.7 hole 1: 1(0,0) 2(2.54,0) 3(5.08,0)
  silkscreen extent -2.29,-2.95 7.37,1.78
TO252 [mm] "DPAK"
  rrect20% 1.5x2.5 smd: 1(-2.3,-6.9) 2(2.3,-6.9)
  rrect20% 7x7 smd: 3(0,0)
  rect 1.6x2.2 hole 1.2 square: 4(-6.934,-1.549) 5(6.566,-1.549)
  silkscreen extent -6.88,-8.46 6.6,3.8, body extent -3.37,-7.38 3.36,2.72, height 2.37
TO-263-5 [mm]
  rect 1.1x2.8 smd: 1(-3.4,0) 2(-1.7,0) 3(0,0) 4(1.7,0) 5(3.4,0)
  rect 10.8x9 smd: 6(0,11.2)
  silkscreen extent -5.9,-1.9 5.9,16.2, body extent -5.08,-0.32 5.08,14.32, height 4.57
tpd [mm]
  round 1 smd: 1(0,0)
VH-AW-3.96*2P [mm]
  oval 2.5x4 hole 1.8: 1(-5.94,0) 2(-1.98,0)
  silkscreen extent -7.89,-4.8 0.08,3.7
VH-AW-3.96*6P [mm]
  oval 2.5x4 hole 1.8: 1(-5.94,0) 2(-1.98,0) 3(1.98,0) 4(5.94,0) 5(9.9,0) 6(13.86,0)
  silkscreen extent -7.89,-4.8 15.82,3.7
XH2.54-4A [mm]
  rect 1.5x1.5 hole 0.8: 1(-3.75,0)
  round 1.5 hole 0.8: 2(-1.25,0) 3(1.25,0) 4(3.75,0)
  silkscreen extent -6.25,-2.4 6.25,3.4, body extent -6.2,-2.35 6.2,3.4, height 7.1
XTAL-3225-2 [mm]
  rect 1.5x2.5 smd: 1(-1.2,0) 2(1.2,0)
  silkscreen extent -1.6,-1.5 1.6,1.5, body extent -1.6,-1.25 1.6,1.25, height 0.9

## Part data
C1 C2 C7 C11 C18 C19 C20 C21 C41 C42 C43 C44: library part CAP2, "电解电容"
C3 C4 C6 C8 C9 C10 C12 C13 C46: library part CAP4, "贴片电容 10%"
C5 C14 C15 C16 C17 C37 C38 C39 C40 C45 C51 C52 C55 C56 C57: library part CAP4, "贴片电容 20%"
C22 C23 C24 C25 C26 C27 C28 C29 C30 C31 C32 C33 C34 C35: library part CAP
C36 C50: library part CAP4, "贴片电容 5%"
C47: library part "0805 22uF (226) 20% 25V", "贴片电容 10%"
D3: library part DIODE
D6 D7 D8 D9 D10 D11 D12 D13: library part DIODE2, "贴片二极管"
D14 D15 D16 D17 D18 D19: library part D_ESD
L1: library part IND
L3: library part CIZHU1, "磁珠电感 100R 100MHz"
P1 P2: library part SIP-2, "XH2.54 2P 直插"
P3 P17: library part HDR1*3
P4: library part HDR1*4
P5: "Header, 6-Pin"
P7 P14: "Header, 8-Pin"
P8 P9 P10: "XH2.54 2P 立贴"
P11: "Header, 12-Pin"
P12 P13: "Header, 5-Pin"
Q1 Q2 Q3 Q4 Q5 Q6 Q7 Q8 Q15 Q16 Q17 Q18 Q19 Q20: library part "MOSFET N", "MOSFET N"
Q9 Q10 Q11 Q12 Q13: library part NPN-1, "三极管"
Q14: library part NPN-1, "NPN"
R1 R13 R15 R26 R27 R28 R29 R30 R47 R53 R60 R61 R62 R64 R65 R66 R67 R68 R69 R70 R71 R72 R73 R74 R75 R76 R77 R83 R87 R88 R89 R90 R91 R95 R99 R100 R101 R102 R103 R107 R111 R112 R113 R114: library part RES
R5 R6 R7 R8 R14 R16 R23 R25: library part RES0, "贴片电阻 1%"
R9 R10 R11 R12 R78 R79: library part RES2, "贴片电阻 5%"
R18 R24 R56 R57 R58 R59: library part RES0, "贴片电阻 5%"
R19 R22 R50: library part "0603 10KΩ (1002) 1%", "贴片电阻 5%"
R31 R32 R33 R34 R35 R36 R37 R38 R39 R40 R41 R42 R43 R44 R45 R46 R48: library part RES-SOP, "贴片电阻 5%"
SWD1: library part SIP-4, "ISP 下载"
TVS1 TVS2 TVS3 TVS4 TVS5 TVS6 TVS7 TVS8 TVS9 TVS10 TVS12: library part TVS-1, "TVS"
TVS11: library part TVS-1, "TVS 5.0V"
U1: library part LM2596
U8: library part TP8485E-SR
U10: library part STM32F405VGTx
U11: library part LM358, "运放"
VR1: library part LM1117, "三端稳压器"
Y1: library part XTAL, "3225 贴片晶振"

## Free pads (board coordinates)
  round 4 hole 3: 0(3.5,3.5) 0(3.5,96.5) 0(146.5,3.5) 0(146.5,96.5)

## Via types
v1: diameter 0.762, hole 0.508, Top Layer to Bottom Layer, tented both sides, 1838 vias
v2: diameter 0.508, hole 0.305, Top Layer to Bottom Layer, tented both sides, 135 vias
v3: diameter 1.016, hole 0.635, Top Layer to Bottom Layer, tented both sides, 63 vias
v4: diameter 2.032, hole 1.524, Top Layer to Bottom Layer, tented both sides, 4 vias
v5: diameter 1.27, hole 0.762, Top Layer to Bottom Layer, tented both sides, 4 vias
v6: diameter 2.54, hole 2.032, Top Layer to Bottom Layer, tented both sides, 1 vias

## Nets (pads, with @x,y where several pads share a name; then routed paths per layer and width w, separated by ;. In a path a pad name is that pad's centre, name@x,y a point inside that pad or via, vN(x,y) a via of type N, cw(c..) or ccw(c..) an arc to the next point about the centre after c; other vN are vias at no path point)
3.3V: C5.2 C10.2 C22.1 C29.1 C33.1 C51.2 C52.2 C55.2 C56.2 C57.2 L3.1 P4.4 R5.1 R6.1 R15.1 R48.2 R61.2 R73.2 R78.2 SWD1.1 U3.16 U8.8 U9.8 U10.6 U10.11 U10.19 U10.28 U10.50 U10.75 U10.100 VR1.2 VR1.4 | length 396.8
  Top Layer w0.254: R48.2@39.952,14.785 ccw(c39.519,15.218) 40.132,15.218 ccw(c40.745,15.218) R48.2@40.312,14.785 ; v2@40.042,16.547 cw(c39.825,16.33) 40.132,16.33 cw(c40.439,16.33) v2@40.222,16.547 ; R48.2@40.132,14.605 v2(40.132,16.637) ; R78.2@72.718,29.792 cw(c72.285,29.359) 72.898,29.359 cw(c73.511,29.359) R78.2@73.078,29.792 ; R78.2@72.898,29.972 72.898,23.876 v2(73.533,23.241) ; v2@73.406,23.241 ccw(c73.099,23.241) 73.316,23.458 ccw(c73.533,23.675) v2@73.533,23.368 ; C52.2@78.941,25.091 ccw(c78.508,25.524) 79.121,25.524 ccw(c79.734,25.524) C52.2@79.301,25.091 ; v2@79.031,25.564 cw(c78.814,25.347) 79.121,25.347 cw(c79.428,25.347) v2@79.211,25.564 ; v2@79.031,25.744 ccw(c78.814,25.961) 79.121,25.961 ccw(c79.428,25.961) v2@79.211,25.744 ; C52.2@79.275,24.671 cw(c79.559,24.295) 79.892,24.629 ; C52.2@79.324,24.74 cw(c79.629,24.511) 79.629,24.892 ; C52.2@79.324,25.044 ccw(c79.629,25.273) 79.629,24.892 ; 79.687,24.834 ccw(c79.382,24.53) 79.121,24.873 cw(c79.316,24.162) 79.838,24.683 ; L3.1@80.592,23.315 ccw(c80.159,22.882) 80.159,23.495 ccw(c80.159,24.108) L3.1@80.592,23.675 ; L3.1@80.772,23.495 80.137,23.495 79.883,23.749 79.883,24.638 79.629,24.892 ; U10.19@81.223,33.322 79.629,33.322 78.486,32.179 78.486,27.051 79.121,26.416 v2(79.121,25.654) C52.2@79.121,24.892 79.629,24.892 ; 81.751,26.046 cw(c80.743,25.038) C51.2@82.169,25.038 ; 82.185,25.613 cw(c81.61,25.038) C51.2@82.423,25.038 ; C51.2@82.423,25.019 82.423,25.375 81.813,25.984 81.813,26.391 82.728,27.305 83.363,27.305 83.773,27.715 U10.28@83.773,28.772 ; 82.773,41.783 92.71,41.783 93.249,42.322 U10.75@96.323,42.322
  Top Layer w0.381: C56.2@74.422,41.529 76.454,41.529 78.689,39.294 79.459,39.294 79.98,39.815 80.333,39.815 80.34,39.822 U10.6@81.223,39.822 82.479,39.822 82.773,39.528 ; C56.2@74.576,41.394 cw(c74.901,41.069) 74.901,41.529 cw(c74.901,41.989) C56.2@74.576,41.664 ; U10.19@81.223,33.322 82.852,33.322 83.82,34.29 83.82,36.799 82.773,37.846 ; U10.11@81.223,37.322 82.534,37.322 82.773,37.561 82.773,37.846 ; C57.2@82.669,47.979 cw(c82.419,47.729) 82.773,47.729 ; 82.773,47.579 cw(c83.339,47.579) C57.2@82.939,47.979 ; C57.2@82.804,48.133 82.773,48.102 U10.100@82.773,43.872 82.773,41.783 82.773,39.528 ; U10.50@94.773,28.772 94.773,27.401 95.885,26.289 C55.2@95.885,25.019 96.52,25.019 96.952,24.587 v3(96.952,22.352) ; C55.2@95.75,25.173 ccw(c95.425,25.498) 95.885,25.498 ccw(c96.345,25.498) C55.2@96.02,25.173 ; C55.2@96.02,24.884 cw(c96.345,24.559) 96.345,25.019 cw(c96.345,25.479) C55.2@96.02,25.154 ; v3@96.727,22.577 ccw(c96.185,23.119) 96.952,23.119 ccw(c97.718,23.119) v3@97.176,22.577 ; 82.773,37.846 82.773,39.528
  Top Layer w0.508: R6.1@13.716,15.367 R5.1@13.716,17.399 v2(15.24,17.399) ; v1(21.463,20.777) VR1.4@21.463,29.591 ; L3.1@80.772,23.641 ccw(c80.772,24.3) 81.238,23.834 ; L3.1@80.881,23.41 ccw(c81.405,23.093) 80.972,22.66 ; 81.28,22.352 80.772,22.86 L3.1@80.772,23.495 80.899,23.495 C51.2@82.423,25.019 ; U3.16@119.091,47.371 120.523,47.371 120.904,46.99 C22.1@122.682,46.99 ; 120.61,28.281 cw(c121.793,27.098) C29.1@121.793,28.771 ; 121.01,28.681 cw(c121.521,28.17) C29.1@121.761,28.851 ; C29.1@121.793,29.113 ccw(c121.793,29.526) C29.1@122.085,29.234 ; R61.2@123.293,22.733 123.293,22.074 122.936,21.717 116.756,21.717 115.697,22.776 v1(115.697,23.419) 115.697,27.305 ; R73.2@123.293,30.494 123.293,30.442 C29.1@121.793,28.942 121.271,28.942 119.634,27.305 U8.8@118.653,27.305 115.697,27.305 ; R15.1@124.182,41.021 v1(124.182,39.778) 121.793,37.389 C33.1@121.793,36.703 119.634,36.703 118.653,35.722 U9.8@118.653,34.629 117.306,34.629 116.713,34.036 116.713,29.462 115.697,28.446 115.697,27.305
  Top Layer w0.762: 81.28,22.352 v3(85.979,22.352)
  Top Layer w1.016: VR1.2@25.808,29.605 28.081,29.605 v3(28.448,29.972) ; 27.562,29.605 ccw(c27.562,30.858) v3(28.448,29.972) ; v3(27.813,46.863) 30.353,44.323 30.353,33.655 30.099,33.401 30.099,29.972 ; C10.2@30.886,27.229 30.785,27.127 29.972,27.127 30.099,27.254 30.099,29.972 ; v3(57.531,49.403) 77.089,49.403 v3(77.343,49.149) ; 76.73,49.403 cw(c76.73,48.536) v3(77.343,49.149) ; C57.2@82.804,48.133 78.359,48.133 v3(77.343,49.149) ; v3(94.234,62.738) 94.234,59.69 98.425,55.499 SWD1.1@98.425,54.356 ; v3(28.448,29.972) 30.099,29.972
  Bottom Layer w0.254: v2(73.533,23.241) 75.946,25.654 v2(79.121,25.654) ; v2@73.533,23.368 ccw(c73.533,23.675) 73.75,23.458 ccw(c73.967,23.241) v2@73.66,23.241 ; v2@79.031,25.564 ccw(c78.814,25.347) 78.814,25.654 ccw(c78.814,25.961) v2@79.031,25.744
  Bottom Layer w0.508: v2(15.24,17.399) 18.085,17.399 v1(21.463,20.777) 21.593,20.907 33.429,20.907 37.699,16.637 v2(40.132,16.637) ; v1(121.437,46.939) 121.437,43.332 124.182,40.588 v1(124.182,39.778)
  Bottom Layer w0.762: v3(85.979,22.352) v3(96.952,22.352) 100.228,22.352 103.632,25.756 109.068,25.756 111.455,23.368 113.995,23.368 ; v3(94.234,62.738) 94.234,67.056 94.996,67.818 94.996,92.71 98.552,96.266 P4.4@103.692,96.266 ; 113.995,23.393 v1@115.748,23.393
  Bottom Layer w1.016: v3(27.813,46.863) 50.394,46.863 52.934,49.403 v3(57.531,49.403) ; v3(77.343,49.149) 80.518,52.324 96.393,52.324 SWD1.1@98.425,54.356
ADC_ELE: U10.33 | length 102.3
  Top Layer w0.254: v2@85.762,25.744 ccw(c85.545,25.961) 85.852,25.961 ccw(c86.159,25.961) v2@85.942,25.744 ; v2(85.852,25.654) 85.852,26.289 86.273,26.71 U10.33@86.273,28.772 ; v2(91.948,68.453) v2(104.648,68.453) ; v2@92.038,68.363 cw(c92.255,68.146) 92.255,68.453 cw(c92.255,68.76) v2@92.038,68.543 ; v2@104.558,60.743 cw(c104.341,60.526) 104.648,60.526 cw(c104.955,60.526) v2@104.738,60.743 ; v2@104.558,68.363 ccw(c104.341,68.146) 104.341,68.453 ccw(c104.341,68.76) v2@104.558,68.543 ; v2(104.648,60.833) 104.648,58.039 105.791,56.896 105.689,56.794 105.689,27.203 v2(105.639,27.153) ; v2@105.549,27.242 ccw(c105.209,27.582) 105.689,27.582
  Top Layer w0.508: 91.948,82.804 v2(91.948,83.629) 91.948,84.455
  Bottom Layer w0.254: v2@85.762,25.564 cw(c85.545,25.347) 85.852,25.347 cw(c86.159,25.347) v2@85.942,25.564 ; v2(85.852,25.654) 85.852,24.571 86.428,23.995 100.601,23.995 103.759,27.153 v2(105.639,27.153) ; v2@91.858,68.543 ccw(c91.641,68.76) 91.948,68.76 ccw(c92.255,68.76) v2@92.038,68.543 ; v2@91.858,83.54 cw(c91.641,83.323) 91.948,83.323 cw(c92.255,83.323) v2@92.038,83.54 ; v2(91.948,68.453) v2(91.948,83.629) ; v2@104.558,60.923 ccw(c104.341,61.14) 104.648,61.14 ccw(c104.955,61.14) v2@104.738,60.923 ; v2@104.558,68.363 cw(c104.341,68.146) 104.648,68.146 cw(c104.955,68.146) v2@104.738,68.363 ; v2(104.648,60.833) v2(104.648,68.453) ; v2@105.549,27.063 ccw(c105.332,26.846) 105.332,27.153 ccw(c105.332,27.459) v2@105.549,27.242
CVALUE1O2: D9.1 P11.3 Q9.3 | length 21.6
  Top Layer w0.762: Q9.3@51.435,13.405 56.214,13.405 D9.1@56.515,13.706 56.515,12.903 60.554,8.865 64.237,8.865 67.132,5.969 P11.3@67.132,3.888
CVALUE2O2: D10.1 P11.5 Q10.3 | length 21.4
  Top Layer w0.762: Q10.3@63.246,13.278 Q10.3@63.373,13.405 63.674,13.706 D10.1@68.294,13.706 68.294,10.471 72.212,6.553 P11.5@72.212,3.888 ; D10.1@67.607,13.268 ccw(c66.55,12.212) 66.55,13.706 ccw(c66.55,15.2) D10.1@67.607,14.144 ; D10.1@67.857,13.268 cw(c66.8,12.212) 68.294,12.212 cw(c69.789,12.212) D10.1@68.732,13.268
CVALUE3O2: D11.1 P11.7 Q11.3 | length 17.7
  Top Layer w0.762: P11.7@77.292,3.788 77.292,9.881 80.073,12.662 ; D11.1@79.776,13.163 cw(c79.503,12.662) 80.073,12.662 ; D11.1@80.371,13.163 ccw(c80.644,12.662) 80.073,12.662 ; Q11.3@75.311,13.405 75.311,13.183 75.279,13.151 75.279,13.373 Q11.3@75.311,13.405 ; Q11.3@75.311,13.405 79.772,13.405 D11.1@80.073,13.706 80.073,12.662
CVALUE4O2: D12.1 P11.9 Q12.3 | length 16.4
  Top Layer w0.762: P11.9@82.372,3.788 82.372,7.214 87.249,12.09 Q12.3@87.249,13.405 91.552,13.405 D12.1@91.853,13.706
CVALUE5O2: D13.1 P11.11 Q13.3 | length 24.3
  Top Layer w0.762: P11.11@87.452,3.788 87.452,5.71 88.245,6.502 97.003,6.502 99.219,8.719 Q13.3@99.219,10.941 ; Q13.3@99.187,10.941 Q13.3@99.219,10.941 ; D13.1@103.331,13.405 D13.1@103.632,13.706 103.632,11.76 102.813,10.941 Q13.3@99.219,10.941
EN1_485: R71.1 U8.2 U8.3 U10.56 | length 32.8
  Top Layer w0.254: U10.56@96.323,32.822 97.48,32.822 98.552,31.75 v2(98.552,25.654) ; v2@98.462,25.744 ccw(c98.245,25.961) 98.552,25.961 ccw(c98.859,25.961) v2@98.642,25.744 ; R71.1@109.855,26.67 v2(110.871,26.67) 111.506,26.035 U8.2@112.903,26.035 U8.3@112.903,24.765 ; R71.1@110.013,26.512 cw(c110.393,26.132) 110.393,26.67 cw(c110.393,27.208) R71.1@110.013,26.828 ; v2@110.781,26.58 ccw(c110.564,26.363) 110.564,26.67 ccw(c110.564,26.977) v2@110.781,26.76 ; v2@110.871,26.543 cw(c110.871,26.236) 111.088,26.453 cw(c111.305,26.67) v2@110.998,26.67 ; U8.2@112.387,25.9 ccw(c112.062,25.575) 112.062,26.035 ccw(c112.062,26.495) U8.2@112.387,26.17 ; U8.3@112.768,24.9 ccw(c112.443,25.225) 112.903,25.225 ccw(c113.363,25.225) U8.3@113.038,24.9 ; U8.2@112.768,25.9 cw(c112.443,25.575) 112.903,25.575 cw(c113.363,25.575) U8.2@113.038,25.9
  Bottom Layer w0.254: v2(98.552,25.654) 101.371,28.473 109.118,28.473 v2@110.871,26.721 ; v2@98.552,25.781 ccw(c98.552,26.088) 98.769,25.871 ccw(c98.986,25.654) v2@98.679,25.654 ; 110.618,26.974 cw(c110.315,26.67) v2@110.744,26.67
EN2_485: R77.1 U9.2 U9.3 U10.57 | length 23.9
  Top Layer w0.254: U10.57@96.323,33.322 v2(98.123,33.322) ; v2@98.033,33.232 ccw(c97.816,33.015) 97.816,33.322 ccw(c97.816,33.629) v2@98.033,33.412 ; R77.1@109.855,33.147 v2(110.871,33.147) 111.125,33.147 111.337,33.359 ; R77.1@110.013,32.989 cw(c110.393,32.609) 110.393,33.147 cw(c110.393,33.685) R77.1@110.013,33.305 ; v2@110.781,33.057 ccw(c110.564,32.84) 110.564,33.147 ccw(c110.564,33.454) v2@110.781,33.237 ; v2@110.915,33.266 ccw(c111.053,33.642) 111.337,33.359 ; U9.2@112.387,33.224 ccw(c112.062,32.899) 112.062,33.359 ccw(c112.062,33.819) U9.2@112.387,33.494 ; U9.3@112.768,32.224 ccw(c112.443,32.549) 112.903,32.549 ccw(c113.363,32.549) U9.3@113.038,32.224 ; U9.2@112.768,33.224 cw(c112.443,32.899) 112.903,32.899 cw(c113.363,32.899) U9.2@113.038,33.224 ; U9.3@112.903,32.089 U9.2@112.903,33.359 111.337,33.359
  Bottom Layer w0.254: v2(98.123,33.322) 110.696,33.322 v2(110.871,33.147) ; v2@98.213,33.232 cw(c98.43,33.015) 98.43,33.322 cw(c98.43,33.629) v2@98.213,33.412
